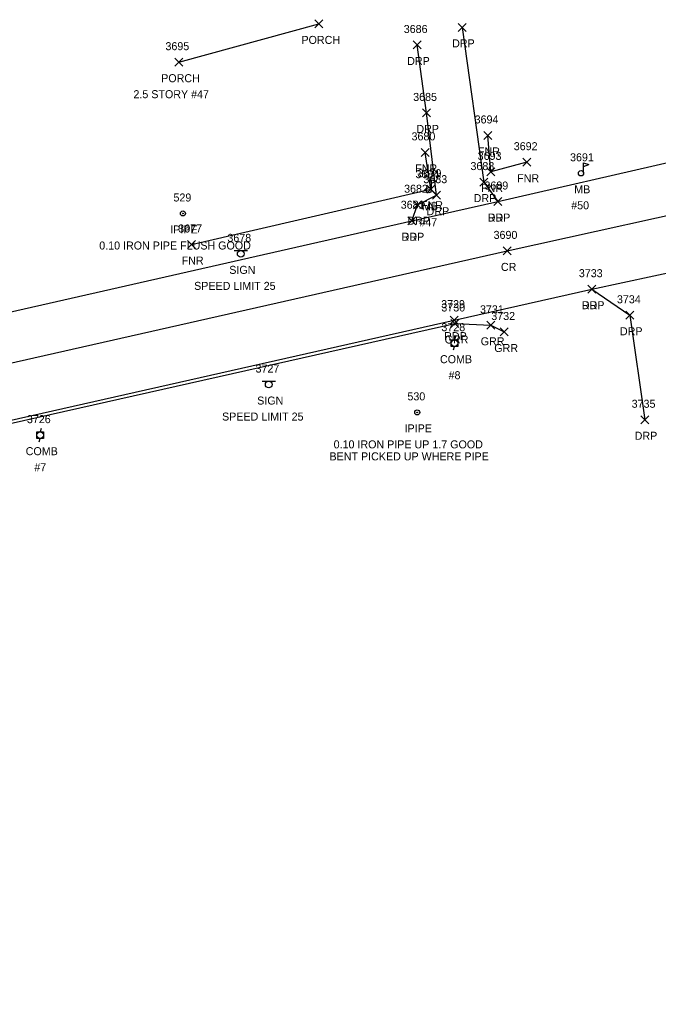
# Model space of a CAD drawing. Extents: x 1690689 to 1696275, y 438760 to 444007.
# Drawn here: x 1691858.3 to 1692017.8, y 442358.8 to 442607.8 of the extents above; entities that cross this region are included whole.
import ezdxf

# ---------------------------------------------------------------- set-up
doc = ezdxf.new("R2010")
doc.units = 0
for name, color, linetype in [('L_A', 7, 'Continuous'), ('L_C', 7, 'Continuous'), ('L_I', 7, 'Continuous'), ('L_TIC', 7, 'Continuous'), ('LBF', 7, 'Continuous'), ('LFNC', 7, 'Continuous'), ('LMB', 7, 'Continuous'), ('M_A', 7, 'Continuous'), ('M_C', 7, 'Continuous'), ('M_I', 7, 'Continuous'), ('MPIP', 7, 'Continuous'), ('P_A', 7, 'Continuous'), ('P_I', 7, 'Continuous'), ('P_TIC', 7, 'Continuous'), ('PET', 7, 'Continuous'), ('PRC', 7, 'Continuous'), ('R_A', 7, 'Continuous'), ('R_I', 7, 'Continuous'), ('R_TIC', 7, 'Continuous'), ('RDP', 7, 'Continuous'), ('RGR', 7, 'Continuous'), ('S_A', 7, 'Continuous'), ('S_C', 7, 'Continuous'), ('S_I', 7, 'Continuous'), ('SSGN', 7, 'Continuous'), ('U_A', 7, 'Continuous'), ('U_C', 7, 'Continuous'), ('U_I', 7, 'Continuous'), ('UP', 7, 'Continuous')]:
    doc.layers.add(name, color=color, linetype=linetype)

msp = doc.modelspace()

# ---------------------------------------------------------------- linework, layer by layer
at = {"layer": 'L_TIC'}
for points in [[(1691932, 442605.76), (1691934, 442607.76)], [(1691934, 442605.76), (1691932, 442607.76)], [(1691896.95, 442596.19), (1691898.95, 442598.19)], [(1691898.95, 442596.19), (1691896.95, 442598.19)], [(1691974.23, 442577.88), (1691976.23, 442579.88)], [(1691976.23, 442577.88), (1691974.23, 442579.88)], [(1691958.55, 442573.65), (1691960.55, 442575.65)], [(1691960.55, 442573.65), (1691958.55, 442575.65)], [(1691984.01, 442571.19), (1691986.01, 442573.19)], [(1691986.01, 442571.19), (1691984.01, 442573.19)], [(1691974.98, 442568.77), (1691976.98, 442570.77)], [(1691976.98, 442568.77), (1691974.98, 442570.77)], [(1691959.98, 442564.44), (1691961.98, 442566.44)], [(1691961.98, 442564.44), (1691959.98, 442566.44)], [(1691900.15, 442550.62), (1691902.15, 442552.62)], [(1691902.15, 442550.62), (1691900.15, 442552.62)]]:
    msp.add_lwpolyline(points, dxfattribs=at)
at = {"layer": 'LBF'}
msp.add_lwpolyline([(1691897.95, 442597.19), (1691933, 442606.76)], dxfattribs=at)
at = {"layer": 'LFNC'}
for points in [[(1691985.01, 442572.19), (1691975.98, 442569.77), (1691975.23, 442578.88)], [(1691901.15, 442551.62), (1691960.98, 442565.44), (1691959.55, 442574.65)]]:
    msp.add_lwpolyline(points, dxfattribs=at)
at = {"layer": 'LMB'}
for p, q in [((1691999.16, 442569.43), (1691999.16, 442572.03)), ((1691999.16, 442572.02), (1692000.45, 442571.64)), ((1691999.16, 442571.12), (1692000.45, 442571.63)), ((1691998.51, 442569.42), (1691998.51, 442569.42)), ((1691961.11, 442567.81), (1691962.4, 442567.42)), ((1691961.11, 442565.21), (1691961.11, 442567.81)), ((1691961.11, 442566.91), (1691962.4, 442567.41)), ((1691960.46, 442565.2), (1691960.46, 442565.2))]:
    msp.add_line(p, q, dxfattribs=at)
for centre in [(1691998.51, 442569.42), (1691960.46, 442565.2)]:
    msp.add_circle(centre, 0.656, dxfattribs=at)
at = {"layer": 'MPIP'}
for centre, radius in [((1691899.01, 442559.37), 0.625), ((1691899.01, 442559.37), 0.0833), ((1691957.57, 442509.66), 0.625), ((1691957.57, 442509.66), 0.0833)]:
    msp.add_circle(centre, radius, dxfattribs=at)
at = {"layer": 'P_TIC'}
for points in [[(1691976.69, 442561.36), (1691978.69, 442563.36)], [(1691978.69, 442561.36), (1691976.69, 442563.36)], [(1691955.19, 442556.56), (1691957.19, 442558.56)], [(1691957.19, 442556.56), (1691955.19, 442558.56)], [(1691979.06, 442549.02), (1691981.06, 442551.02)], [(1691981.06, 442549.02), (1691979.06, 442551.02)], [(1692000.23, 442539.45), (1692002.23, 442541.45)], [(1692002.23, 442539.45), (1692000.23, 442541.45)], [(1691965.82, 442531.71), (1691967.82, 442533.71)], [(1691967.82, 442531.71), (1691965.82, 442533.71)]]:
    msp.add_lwpolyline(points, dxfattribs=at)
at = {"layer": 'PET'}
for points in [[(1691244.99, 442422.42), (1691274.8, 442426.79), (1691288.71, 442428.52), (1691321.88, 442431.22), (1691333.08, 442431.36), (1691372.74, 442436.52), (1691410.43, 442441.3), (1691430.74, 442444.46), (1691471.26, 442451.19), (1691485.27, 442453.88), (1691572.21, 442470.9), (1691593.06, 442475.96), (1691664.16, 442491.04), (1691682.81, 442495.5), (1691724.04, 442504.48), (1691768.38, 442514.48), (1691786.16, 442518.76), (1691792.23, 442520.23), (1691811.17, 442524.66), (1691956.19, 442557.56), (1691977.69, 442562.36), (1692021.28, 442572.37)], [(1691262.71, 442389.79), (1691278.62, 442392.36), (1691323.95, 442400.43), (1691413.56, 442412.73), (1691416.45, 442413.87), (1691418.24, 442414.27), (1691431.74, 442416.27), (1691440.51, 442417.83), (1691444.91, 442417.31), (1691446.93, 442416.56), (1691480.01, 442421.07), (1691541.54, 442433.59), (1691592.5, 442446.57), (1691666.55, 442464.92), (1691770.02, 442488.32), (1691794.27, 442493.8), (1691844.9, 442505.22), (1691966.82, 442532.71), (1692001.23, 442540.45), (1692024.42, 442545.45)]]:
    msp.add_lwpolyline(points, dxfattribs=at)
at = {"layer": 'PRC'}
msp.add_lwpolyline([(1691130.81, 442358.75), (1691152.44, 442373.63), (1691178.23, 442388.18), (1691209.8, 442400.63), (1691248.04, 442408.48), (1691275.24, 442412.28), (1691309.15, 442415.93), (1691347.17, 442419.98), (1691395.19, 442425.91), (1691433.65, 442431.72), (1691478.76, 442438.88), (1691513.2, 442445.49), (1691566.06, 442456.6), (1691813.76, 442512.5), (1691980.06, 442550.02), (1692039.61, 442563.23)], dxfattribs=at)
at = {"layer": 'R_TIC'}
for points in [[(1691967.8, 442604.9), (1691969.8, 442606.9)], [(1691969.8, 442604.9), (1691967.8, 442606.9)], [(1691956.57, 442600.49), (1691958.57, 442602.49)], [(1691958.57, 442600.49), (1691956.57, 442602.49)], [(1691958.87, 442583.51), (1691960.87, 442585.51)], [(1691960.87, 442583.51), (1691958.87, 442585.51)], [(1691973.18, 442566.22), (1691975.18, 442568.22)], [(1691975.18, 442566.22), (1691973.18, 442568.22)], [(1691961.42, 442562.95), (1691963.42, 442564.95)], [(1691963.42, 442562.95), (1691961.42, 442564.95)], [(1691956.6, 442560.56), (1691958.6, 442562.56)], [(1691958.6, 442560.56), (1691956.6, 442562.56)], [(1691976.69, 442561.36), (1691978.69, 442563.36)], [(1691978.69, 442561.36), (1691976.69, 442563.36)], [(1691955.19, 442556.56), (1691957.19, 442558.56)], [(1691957.19, 442556.56), (1691955.19, 442558.56)], [(1692000.23, 442539.45), (1692002.23, 442541.45)], [(1692002.23, 442539.45), (1692000.23, 442541.45)], [(1692009.75, 442532.93), (1692011.75, 442534.93)], [(1692011.75, 442532.93), (1692009.75, 442534.93)], [(1691965.94, 442530.88), (1691967.94, 442532.88)], [(1691967.94, 442530.88), (1691965.94, 442532.88)], [(1691974.95, 442530.42), (1691976.95, 442532.42)], [(1691976.95, 442530.42), (1691974.95, 442532.42)], [(1691978.34, 442528.75), (1691980.34, 442530.75)], [(1691980.34, 442528.75), (1691978.34, 442530.75)], [(1692013.43, 442506.81), (1692015.43, 442508.81)], [(1692015.43, 442506.81), (1692013.43, 442508.81)]]:
    msp.add_lwpolyline(points, dxfattribs=at)
at = {"layer": 'RDP'}
for points in [[(1691968.8, 442605.9), (1691974.18, 442567.22), (1691977.69, 442562.36)], [(1691956.19, 442557.56), (1691957.6, 442561.56), (1691962.42, 442563.95), (1691959.87, 442584.51), (1691957.57, 442601.49)], [(1692001.23, 442540.45), (1692010.75, 442533.93), (1692014.43, 442507.81)]]:
    msp.add_lwpolyline(points, dxfattribs=at)
at = {"layer": 'RGR'}
msp.add_lwpolyline([(1691834.07, 442496.27), (1691839.14, 442502.22), (1691844.96, 442504.46), (1691966.94, 442531.88), (1691975.95, 442531.42), (1691979.34, 442529.75)], dxfattribs=at)
at = {"layer": 'SSGN'}
for p, q in [((1691911.8, 442550.13), (1691915.13, 442550.13)), ((1691913.45, 442549.3), (1691913.45, 442549.3)), ((1691918.79, 442517.47), (1691922.12, 442517.47)), ((1691920.44, 442516.63), (1691920.44, 442516.63))]:
    msp.add_line(p, q, dxfattribs=at)
for centre in [(1691913.45, 442549.3), (1691920.44, 442516.63)]:
    msp.add_circle(centre, 0.833, dxfattribs=at)
at = {"layer": 'UP'}
for p, q in [((1691966.04, 442526.12), (1691966.04, 442527.78)), ((1691966.04, 442527.78), (1691967.71, 442527.78)), ((1691967.12, 442528.62), (1691966.87, 442527.78)), ((1691966.87, 442526.95), (1691966.87, 442526.95)), ((1691967.71, 442527.78), (1691967.71, 442526.12)), ((1691967.71, 442526.12), (1691966.04, 442526.12)), ((1691966.62, 442525.28), (1691966.87, 442526.12)), ((1691862.49, 442503.12), (1691862.49, 442504.79)), ((1691862.49, 442504.79), (1691864.15, 442504.79)), ((1691863.57, 442505.62), (1691863.32, 442504.79)), ((1691864.15, 442504.79), (1691864.15, 442503.12)), ((1691864.15, 442503.12), (1691862.49, 442503.12)), ((1691863.07, 442502.29), (1691863.32, 442503.12)), ((1691863.32, 442503.96), (1691863.32, 442503.96))]:
    msp.add_line(p, q, dxfattribs=at)
for centre in [(1691966.87, 442526.95), (1691863.32, 442503.96)]:
    msp.add_circle(centre, 0.833, dxfattribs=at)

# ---------------------------------------------------------------- texts
at = {"layer": 'L_A'}
for s, p in [('PORCH', (1691928.63, 442601.76)), ('PORCH', (1691893.57, 442592.19)), ('FNR', (1691972.76, 442573.88)), ('FNR', (1691957.08, 442569.65)), ('FNR', (1691982.55, 442567.19)), ('FNR', (1691973.52, 442564.77)), ('MB', (1691996.82, 442564.42)), ('FNR', (1691958.52, 442560.44)), ('MB', (1691958.77, 442560.2)), ('FNR', (1691898.69, 442546.62))]:
    msp.add_text(s, height=2, dxfattribs=at).set_placement(p)
at = {"layer": 'L_C'}
for s, p in [('2.5 STORY #47', (1691886.64, 442588.19)), ('#50', (1691996.06, 442560.42)), ('#47', (1691958.1, 442556.2))]:
    msp.add_text(s, height=2, dxfattribs=at).set_placement(p)
at = {"layer": 'L_I'}
for s, p in [('3695', (1691894.64, 442600.19)), ('3694', (1691971.92, 442581.88)), ('3680', (1691956.15, 442577.65)), ('3692', (1691981.7, 442575.19)), ('3693', (1691972.68, 442572.77)), ('3691', (1691995.77, 442572.42)), ('3684', (1691957.15, 442568.2)), ('3679', (1691957.67, 442568.44)), ('3677', (1691897.84, 442554.62))]:
    msp.add_text(s, height=2, dxfattribs=at).set_placement(p)
at = {"layer": 'M_A'}
for p in [(1691895.85, 442554.37), (1691954.41, 442504.66)]:
    msp.add_text('IPIPE', height=2, dxfattribs=at).set_placement(p)
at = {"layer": 'M_C'}
for s, p in [('0.10 IRON PIPE FLUSH GOOD', (1691878.09, 442550.37)), ('0.10 IRON PIPE UP 1.7 GOOD', (1691936.68, 442500.66)), ('BENT PICKED UP WHERE PIPE', (1691935.64, 442497.66))]:
    msp.add_text(s, height=2, dxfattribs=at).set_placement(p)
at = {"layer": 'M_I'}
for s, p in [('529', (1691896.64, 442562.37)), ('530', (1691955.12, 442512.66))]:
    msp.add_text(s, height=2, dxfattribs=at).set_placement(p)
at = {"layer": 'P_A'}
for s, p in [('RDP', (1691975.18, 442557.36)), ('RDP', (1691953.67, 442552.56)), ('CR', (1691978.49, 442545.02)), ('RDP', (1691998.72, 442535.45)), ('RDP', (1691964.31, 442527.71))]:
    msp.add_text(s, height=2, dxfattribs=at).set_placement(p)
at = {"layer": 'P_I'}
for s, p in [('3689', (1691974.37, 442565.36)), ('3681', (1691953.45, 442560.56)), ('3690', (1691976.66, 442553.02)), ('3733', (1691997.97, 442543.45)), ('3729', (1691963.55, 442535.71))]:
    msp.add_text(s, height=2, dxfattribs=at).set_placement(p)
at = {"layer": 'R_A'}
for s, p in [('DRP', (1691966.29, 442600.9)), ('DRP', (1691955.06, 442596.49)), ('DRP', (1691957.36, 442579.51)), ('DRP', (1691971.67, 442562.22)), ('DRP', (1691959.91, 442558.95)), ('DRP', (1691975.18, 442557.36)), ('DRP', (1691955.09, 442556.56)), ('DRP', (1691953.67, 442552.56)), ('DRP', (1691998.72, 442535.45)), ('DRP', (1692008.24, 442528.93)), ('GRR', (1691964.43, 442526.88)), ('GRR', (1691973.44, 442526.42)), ('GRR', (1691976.83, 442524.75)), ('DRP', (1692011.92, 442502.81))]:
    msp.add_text(s, height=2, dxfattribs=at).set_placement(p)
at = {"layer": 'R_I'}
for s, p in [('3686', (1691954.2, 442604.49)), ('3685', (1691956.56, 442587.51)), ('3688', (1691970.88, 442570.22)), ('3683', (1691959.11, 442566.95)), ('3682', (1691954.29, 442564.56)), ('3689', (1691974.37, 442565.36)), ('3681', (1691953.45, 442560.56)), ('3733', (1691997.97, 442543.45)), ('3730', (1691963.6, 442534.88)), ('3734', (1692007.49, 442536.93)), ('3731', (1691973.26, 442534.42)), ('3732', (1691976.08, 442532.75)), ('3735', (1692011.17, 442510.81))]:
    msp.add_text(s, height=2, dxfattribs=at).set_placement(p)
at = {"layer": 'S_A'}
for p in [(1691910.59, 442544.28), (1691917.57, 442511.61)]:
    msp.add_text('SIGN', height=2, dxfattribs=at).set_placement(p)
at = {"layer": 'S_C'}
for p in [(1691901.81, 442540.28), (1691908.79, 442507.61)]:
    msp.add_text('SPEED LIMIT 25', height=2, dxfattribs=at).set_placement(p)
at = {"layer": 'S_I'}
for s, p in [('3678', (1691910.12, 442552.28)), ('3727', (1691917.16, 442519.61))]:
    msp.add_text(s, height=2, dxfattribs=at).set_placement(p)
at = {"layer": 'U_A'}
for p in [(1691963.26, 442521.95), (1691859.71, 442498.96)]:
    msp.add_text('COMB', height=2, dxfattribs=at).set_placement(p)
at = {"layer": 'U_C'}
for s, p in [('#8', (1691965.41, 442517.95)), ('#7', (1691861.86, 442494.96))]:
    msp.add_text(s, height=2, dxfattribs=at).set_placement(p)
at = {"layer": 'U_I'}
for s, p in [('3728', (1691963.61, 442529.95)), ('3726', (1691860.01, 442506.96))]:
    msp.add_text(s, height=2, dxfattribs=at).set_placement(p)

doc.saveas('drawing.dxf')
